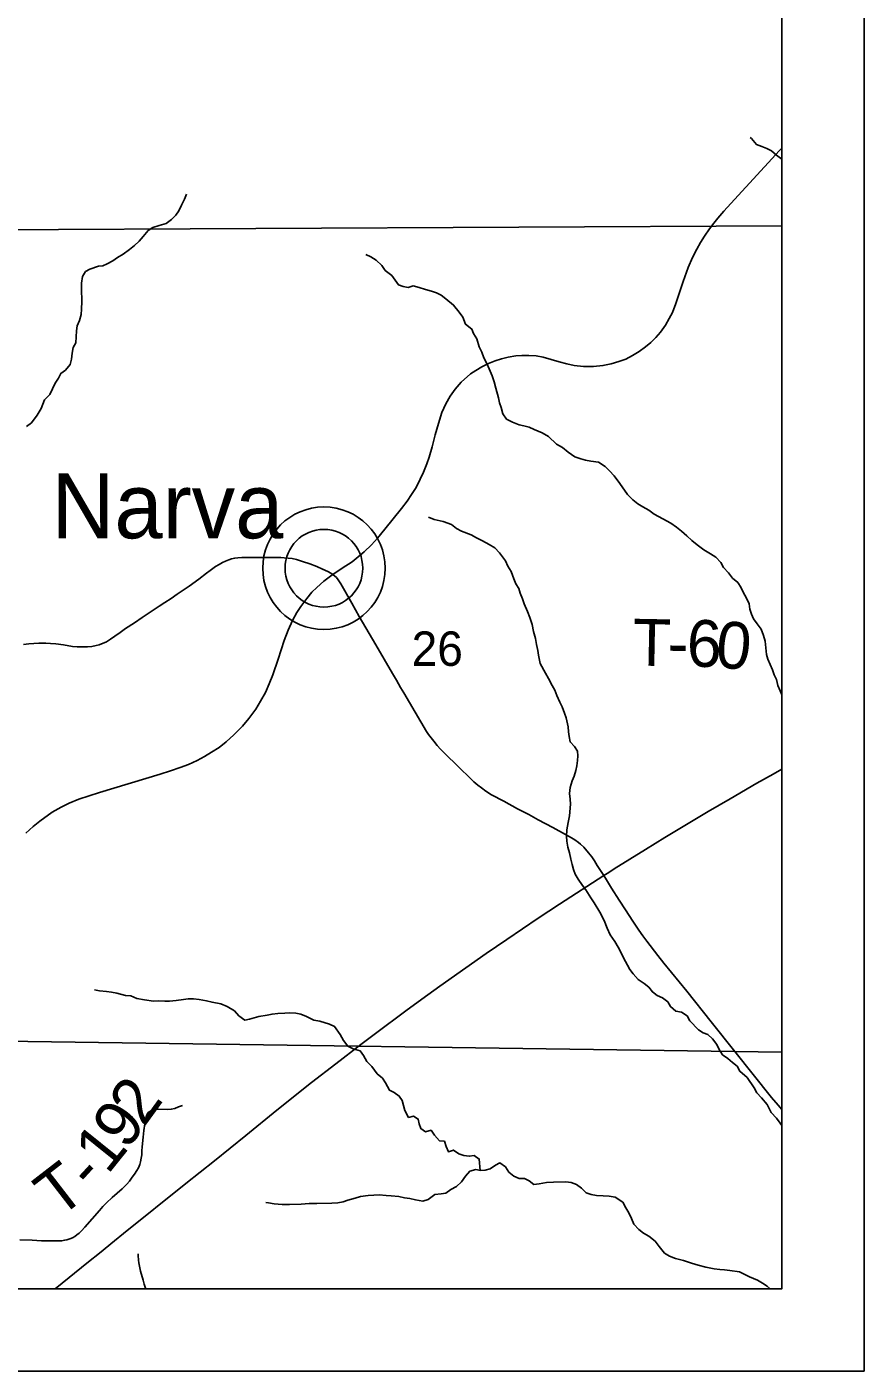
# Model space of a CAD drawing. Extents: x 0 to 34, y 0 to 22.
# Drawn here: x 16.483 to 17.5, y 13.5 to 15.132 of the extents above; entities that cross this region are included whole.
import ezdxf

# ---------------------------------------------------------------- set-up
doc = ezdxf.new("R2010")
doc.units = 0
for name, color, linetype in [('GM_X_Corporation', 7, 'Continuous'), ('GM_X_County_Road', 7, 'Continuous'), ('GM_X_Minor_River', 7, 'Continuous'), ('GM_X_Rail_Line', 7, 'Continuous'), ('GM_X_Section_Text', 7, 'Continuous'), ('GM_X_Township_Road', 7, 'Continuous'), ('GM_X_Township_Road_Text', 7, 'Continuous'), ('GM_X_Unincorporated', 7, 'Continuous'), ('GM_X_Unincorporated_Location', 7, 'Continuous'), ('GM_X_Unincorporated_Text', 7, 'Continuous'), ('GM_X_US_Route', 7, 'Continuous'), ('SH_Data', 7, 'Continuous')]:
    doc.layers.add(name, color=color, linetype=linetype)

msp = doc.modelspace()

# ---------------------------------------------------------------- linework, layer by layer
at = {"layer": 'GM_X_Corporation'}
for points in [[(16.4214, 13.6), (17.4, 13.6), (17.4, 16.913), (16.5516, 16.9243), (16.4689, 16.9245), (16.4603, 16.2617), (16.4611, 16.1288), (16.4516, 15.5964), (16.4498, 15.4626), (16.4419, 14.8642), (16.438, 14.5908), (16.4339, 14.3806), (16.4212, 13.6609)], [(17.4, 14.8906), (17.4, 15.8967), (16.4563, 15.9084), (16.441, 14.8856)], [(17.4, 13.8871), (17.4, 14.8906), (16.441, 14.8856), (16.4262, 13.901)], [(16.4212, 13.6), (17.4, 13.6), (17.4, 13.8871), (16.4262, 13.901)]]:
    msp.add_lwpolyline(points, close=True, dxfattribs=at)
at = {"layer": 'GM_X_County_Road'}
for points in [[(16.4786, 14.3823), (16.4851, 14.3829), (16.4912, 14.3835), (16.4971, 14.3838), (16.5014, 14.3839), (16.5055, 14.3839), (16.5112, 14.3835), (16.5178, 14.383), (16.5272, 14.3818), (16.538, 14.38), (16.5438, 14.3795), (16.5475, 14.3793), (16.5565, 14.3795), (16.5615, 14.38), (16.5668, 14.3809), (16.5703, 14.382), (16.5732, 14.3829), (16.5764, 14.3843), (16.5793, 14.3857), (16.5844, 14.3888), (16.5896, 14.3925), (16.5962, 14.3968), (16.6027, 14.4015), (16.6135, 14.4086), (16.6228, 14.4151), (16.6323, 14.4215), (16.6434, 14.4288), (16.6502, 14.4333), (16.6578, 14.4383), (16.6653, 14.4432), (16.68, 14.453), (16.6915, 14.4616), (16.7009, 14.4687), (16.7053, 14.4721), (16.7118, 14.4768), (16.7163, 14.4796), (16.7202, 14.4818), (16.7241, 14.4836), (16.728, 14.4851), (16.7313, 14.4861), (16.7353, 14.4871), (16.7391, 14.4875), (16.7437, 14.4881), (16.7481, 14.4881), (16.7851, 14.4879), (16.7914, 14.4878), (16.7951, 14.4877), (16.8001, 14.4872), (16.8049, 14.4865), (16.8104, 14.4853), (16.8177, 14.4832), (16.8264, 14.4804), (16.8351, 14.4769), (16.842, 14.4739), (16.8484, 14.4709), (16.8518, 14.4689), (16.8538, 14.4678), (16.8566, 14.4657), (16.859, 14.4635), (16.8611, 14.4608), (16.8641, 14.4561), (16.8774, 14.4323), (16.8866, 14.4162), (16.9066, 14.3819), (16.9268, 14.3472), (16.9317, 14.3389), (16.9367, 14.3302), (16.9406, 14.3235), (16.9475, 14.3117), (16.9682, 14.2766), (16.9708, 14.273), (16.974, 14.2688), (16.9771, 14.2649), (16.9814, 14.2598), (16.9854, 14.2551), (16.9938, 14.2466), (17.0035, 14.2372), (17.0258, 14.2154), (17.0305, 14.2113), (17.0349, 14.2081), (17.0403, 14.2042), (17.0474, 14.1998), (17.0621, 14.1922), (17.079, 14.1828), (17.0924, 14.1757), (17.1039, 14.1695), (17.1217, 14.1601), (17.1371, 14.1516), (17.1445, 14.1477), (17.1486, 14.145), (17.1528, 14.142), (17.1553, 14.1399), (17.1595, 14.1362), (17.1651, 14.1295), (17.1692, 14.1243), (17.1722, 14.1196), (17.1758, 14.1141), (17.1837, 14.1017)], [(17.1837, 14.1017), (17.1868, 14.0965), (17.193, 14.0864), (17.2023, 14.0719), (17.2099, 14.0601), (17.2189, 14.0462), (17.2263, 14.0354), (17.2311, 14.0287), (17.2361, 14.0219), (17.2492, 14.0048), (17.2568, 13.9953), (17.2847, 13.9614), (17.3143, 13.9242), (17.343, 13.8879), (17.3876, 13.8323), (17.3954, 13.8228), (17.4, 13.8175)]]:
    msp.add_lwpolyline(points, dxfattribs=at)
at = {"layer": 'GM_X_Minor_River'}
for points in [[(17.4, 14.9714), (17.3935, 14.9764), (17.3876, 14.9816), (17.3819, 14.9845), (17.3757, 14.987), (17.3692, 14.9895), (17.363, 14.9965), (17.3614, 14.9979)], [(16.6302, 14.8848), (16.6358, 14.8888), (16.6433, 14.8909), (16.652, 14.8934), (16.6583, 14.8985), (16.6635, 14.9035), (16.6675, 14.909), (16.6704, 14.9159), (16.674, 14.9228), (16.6765, 14.929)], [(16.4821, 14.6469), (16.4881, 14.6516), (16.4951, 14.6606), (16.5002, 14.6687), (16.5041, 14.6794), (16.5104, 14.686), (16.5136, 14.6926), (16.5169, 14.6995), (16.5209, 14.7057), (16.5238, 14.7115), (16.5297, 14.7154), (16.5353, 14.7224), (16.537, 14.7289), (16.5376, 14.7362), (16.5389, 14.743), (16.5422, 14.7484), (16.543, 14.7633), (16.5439, 14.7694), (16.5468, 14.7755), (16.5485, 14.7828), (16.5491, 14.7893), (16.5493, 14.7988), (16.5489, 14.814), (16.5491, 14.8212), (16.5504, 14.8289), (16.5537, 14.835), (16.5593, 14.8382), (16.5695, 14.8415), (16.5751, 14.842), (16.5804, 14.8444), (16.5871, 14.848), (16.5927, 14.852), (16.5998, 14.8563), (16.6073, 14.8618), (16.6136, 14.8669), (16.6191, 14.872), (16.6239, 14.8775), (16.6302, 14.8848)], [(17.0654, 14.6557), (17.061, 14.6625), (17.0589, 14.67), (17.0569, 14.6757), (17.0556, 14.6817), (17.0523, 14.6934), (17.0506, 14.7014), (17.0481, 14.7085), (17.0445, 14.7168), (17.0417, 14.7236), (17.0381, 14.7303), (17.0353, 14.7371), (17.0321, 14.7439), (17.0292, 14.7533), (17.0252, 14.7597), (17.0232, 14.7653), (17.0158, 14.7712), (17.0122, 14.7799), (17.0079, 14.7859), (17.0012, 14.7944), (16.9919, 14.8018), (16.9861, 14.8066), (16.9804, 14.8091), (16.9742, 14.8113), (16.967, 14.8134), (16.9593, 14.8158), (16.9521, 14.8176), (16.946, 14.8159), (16.9399, 14.8169), (16.9342, 14.819), (16.9303, 14.8246), (16.926, 14.8302), (16.9182, 14.8365), (16.9139, 14.8425), (16.9069, 14.8491), (16.9004, 14.8528), (16.8946, 14.856)], [(17.4, 14.3211), (17.398, 14.3259), (17.3951, 14.3323), (17.3934, 14.3399), (17.3906, 14.3455), (17.3886, 14.3515), (17.383, 14.3643), (17.3813, 14.37), (17.3807, 14.3783), (17.3798, 14.3863), (17.3777, 14.3931), (17.3748, 14.401), (17.3701, 14.4074), (17.3654, 14.4133), (17.363, 14.419), (17.361, 14.425), (17.3604, 14.4318), (17.3568, 14.4393), (17.3536, 14.445), (17.3501, 14.4517), (17.3465, 14.4577), (17.3399, 14.4629), (17.3352, 14.4692), (17.3293, 14.4759), (17.3258, 14.4819), (17.3199, 14.4882), (17.3134, 14.4923), (17.3053, 14.4974), (17.2972, 14.5033), (17.2906, 14.5084), (17.2844, 14.5144), (17.2782, 14.5199), (17.272, 14.5247), (17.265, 14.5295), (17.2554, 14.5349), (17.245, 14.5404), (17.2385, 14.5452), (17.2311, 14.5496), (17.225, 14.5532), (17.2188, 14.558), (17.2126, 14.5643), (17.2031, 14.5778), (17.1961, 14.5871), (17.1906, 14.593), (17.1852, 14.5986), (17.1774, 14.6037), (17.1679, 14.605), (17.1615, 14.606), (17.1557, 14.6078), (17.1484, 14.6102), (17.1403, 14.6157), (17.1334, 14.6213), (17.1264, 14.6257), (17.1163, 14.6349), (17.1087, 14.6393), (17.0991, 14.6432), (17.0929, 14.6461), (17.0864, 14.6479), (17.0807, 14.6489), (17.0727, 14.6521), (17.0654, 14.6557)], [(17.1268, 14.3203), (17.124, 14.3267), (17.1208, 14.3323), (17.1165, 14.341), (17.1129, 14.3473), (17.1065, 14.3594), (17.1044, 14.3692), (17.1035, 14.3749), (17.1018, 14.3824), (17.1008, 14.3896), (17.0984, 14.3979), (17.0966, 14.4066), (17.0938, 14.4149), (17.0909, 14.4225), (17.0869, 14.4315), (17.0848, 14.4379), (17.082, 14.4447), (17.0804, 14.4504), (17.0768, 14.456), (17.0744, 14.462), (17.0711, 14.471), (17.0672, 14.4774), (17.0643, 14.4838), (17.0569, 14.4935), (17.0514, 14.4998), (17.0445, 14.5038), (17.0364, 14.5082), (17.0291, 14.5118), (17.0226, 14.5155), (17.0107, 14.5197), (17.0046, 14.523), (16.9988, 14.5278), (16.9884, 14.5317), (16.9774, 14.5341), (16.9705, 14.537)], [(17.4, 13.7983), (17.3981, 13.8011), (17.3934, 13.807), (17.3872, 13.8141), (17.382, 13.8239), (17.3754, 13.8317), (17.3695, 13.838), (17.3663, 13.844), (17.3577, 13.8567), (17.3491, 13.8641), (17.3459, 13.8701), (17.3401, 13.8749), (17.3343, 13.8794), (17.3281, 13.8841), (17.3238, 13.8905), (17.321, 13.8965), (17.3159, 13.9036), (17.3101, 13.9088), (17.3043, 13.9109), (17.2986, 13.9142), (17.2884, 13.9254), (17.2848, 13.9314), (17.2779, 13.9358), (17.271, 13.9371), (17.2648, 13.9427), (17.2613, 13.9483), (17.2551, 13.9531), (17.2486, 13.9559), (17.2428, 13.9604), (17.2385, 13.966), (17.2327, 13.9708), (17.2253, 13.9755), (17.2195, 13.9822), (17.2152, 13.9878), (17.2072, 14.0028), (17.2044, 14.0088), (17.2012, 14.0149), (17.1972, 14.0216), (17.1913, 14.0298), (17.1877, 14.0377), (17.1841, 14.0471), (17.1789, 14.0573), (17.1718, 14.0685), (17.1679, 14.0745), (17.1619, 14.0842), (17.1576, 14.0898), (17.1525, 14.0973), (17.1489, 14.1033), (17.1469, 14.109), (17.1452, 14.115), (17.1435, 14.1218), (17.1418, 14.1294), (17.1398, 14.1362), (17.1388, 14.1434), (17.1383, 14.1494), (17.1389, 14.1571), (17.1402, 14.1662), (17.1418, 14.1743), (17.1434, 14.1884), (17.1429, 14.1944), (17.1419, 14.2013), (17.1429, 14.2085), (17.1454, 14.2166), (17.1475, 14.2223), (17.1496, 14.2292), (17.151, 14.235), (17.1519, 14.2414), (17.1522, 14.2472), (17.1517, 14.2528), (17.1481, 14.2585), (17.1427, 14.264), (17.1414, 14.2705), (17.1408, 14.2762), (17.1403, 14.2822), (17.1378, 14.2932), (17.1361, 14.2989), (17.1329, 14.3064), (17.1304, 14.3124), (17.1268, 14.3203)], [(17.0335, 13.7435), (17.0323, 13.7574), (17.0261, 13.7618), (17.0201, 13.7608), (17.0136, 13.7618), (17.0075, 13.764), (17.0009, 13.7684), (16.9949, 13.7663), (16.9921, 13.7727), (16.99, 13.7791), (16.984, 13.7797), (16.9781, 13.7864), (16.9738, 13.7924), (16.967, 13.7907), (16.9612, 13.7944), (16.9592, 13.8004), (16.9583, 13.8061), (16.9525, 13.8094), (16.9465, 13.8081), (16.9421, 13.8163), (16.9387, 13.8284), (16.9352, 13.834), (16.929, 13.8384), (16.9233, 13.841), (16.9185, 13.85), (16.9149, 13.8556), (16.9083, 13.8611), (16.9017, 13.8697), (16.8958, 13.876), (16.8915, 13.8831), (16.8875, 13.8887), (16.8791, 13.8912), (16.8726, 13.8945), (16.8675, 13.9016), (16.8635, 13.9087), (16.8565, 13.9184), (16.8503, 13.9213), (16.8385, 13.9248), (16.8312, 13.9261), (16.8224, 13.9305), (16.8155, 13.9333), (16.8094, 13.9347), (16.8022, 13.9349), (16.7961, 13.9348), (16.7874, 13.9342), (16.7806, 13.9336), (16.7745, 13.9323), (16.7647, 13.9306), (16.7587, 13.9289), (16.753, 13.9272), (16.7474, 13.9263), (16.7404, 13.9315), (16.735, 13.9374), (16.7261, 13.9429), (16.7184, 13.9461), (16.7078, 13.9478), (16.7009, 13.9495), (16.6921, 13.9512), (16.6853, 13.9522), (16.6788, 13.952), (16.6728, 13.9511), (16.6641, 13.9501), (16.6561, 13.9491), (16.6501, 13.949), (16.6421, 13.9496), (16.6364, 13.9494), (16.6257, 13.9507), (16.6162, 13.9523), (16.6089, 13.9556), (16.6025, 13.9562), (16.5918, 13.9589), (16.5853, 13.9603), (16.5796, 13.9609), (16.5708, 13.9618), (16.5647, 13.9628)], [(17.3857, 13.6), (17.3822, 13.6033), (17.3764, 13.6066), (17.3706, 13.6103), (17.3607, 13.6146), (17.3484, 13.6207), (17.337, 13.622), (17.3305, 13.6229), (17.3248, 13.6232), (17.3179, 13.6242), (17.3076, 13.6262), (17.2985, 13.6286), (17.2904, 13.6311), (17.2805, 13.6342), (17.2709, 13.6367), (17.2637, 13.6395), (17.2575, 13.6432), (17.2509, 13.6514), (17.2461, 13.6577), (17.2384, 13.664), (17.2319, 13.6676), (17.2261, 13.6721), (17.2202, 13.6784), (17.2174, 13.6855), (17.2142, 13.6923), (17.2106, 13.6983), (17.2066, 13.705), (17.1974, 13.7113), (17.1901, 13.7126), (17.1829, 13.7128), (17.1749, 13.7134), (17.1685, 13.7144), (17.1623, 13.7165), (17.1565, 13.722), (17.1503, 13.7265), (17.1442, 13.729), (17.1377, 13.7299), (17.1226, 13.7296), (17.1142, 13.729), (17.1052, 13.7276), (17.0987, 13.7267), (17.0929, 13.7311), (17.0872, 13.734), (17.0807, 13.7338), (17.0742, 13.7367), (17.0684, 13.7415), (17.0641, 13.7479), (17.0575, 13.7527), (17.0519, 13.7499), (17.0455, 13.7455), (17.0395, 13.7438), (17.0338, 13.7437), (17.0281, 13.7447), (17.0209, 13.7426), (17.0158, 13.7368), (17.0106, 13.7298), (17.0047, 13.724), (16.998, 13.7204), (16.9916, 13.716), (16.986, 13.7151), (16.9784, 13.7145), (16.9702, 13.7083), (16.9638, 13.7062), (16.955, 13.7079), (16.9478, 13.7096), (16.9417, 13.7106), (16.9348, 13.7119), (16.9253, 13.7128), (16.9192, 13.7134), (16.9109, 13.714), (16.9044, 13.7138), (16.8972, 13.7133), (16.8881, 13.7119), (16.8817, 13.7099), (16.8727, 13.7077), (16.8671, 13.7057), (16.8606, 13.7044), (16.8531, 13.7038), (16.8349, 13.7034), (16.8258, 13.7035), (16.8159, 13.7029), (16.8019, 13.7025)], [(16.8019, 13.7025), (16.7928, 13.7023), (16.7833, 13.7032), (16.7764, 13.7042), (16.7732, 13.7049)]]:
    msp.add_lwpolyline(points, dxfattribs=at)
at = {"layer": 'GM_X_Rail_Line'}
msp.add_lwpolyline([(16.4813, 14.1531), (16.4903, 14.1614), (16.4984, 14.1679), (16.5134, 14.1786), (16.5245, 14.1847), (16.5342, 14.1895), (16.5458, 14.1944), (16.5708, 14.2025), (16.6445, 14.2248), (16.6573, 14.2288), (16.6691, 14.2329), (16.6789, 14.2366), (16.6896, 14.2414), (16.6986, 14.2461), (16.7071, 14.2514), (16.7163, 14.2574), (16.7247, 14.2642), (16.7343, 14.2727), (16.7445, 14.2831), (16.7525, 14.2924), (16.7609, 14.3039), (16.7667, 14.3135), (16.7726, 14.3239), (16.7771, 14.3344), (16.7817, 14.3455), (16.788, 14.3646), (16.7954, 14.387), (16.8001, 14.3996), (16.8055, 14.4116), (16.8107, 14.4212), (16.8155, 14.4285), (16.8227, 14.4381), (16.829, 14.4458), (16.835, 14.4516), (16.8433, 14.4591), (16.8532, 14.4665), (16.8659, 14.475), (16.8778, 14.4826), (16.8926, 14.4946), (16.9013, 14.5033), (16.9085, 14.5115), (16.9177, 14.5224), (16.9377, 14.5474), (16.9446, 14.5565), (16.95, 14.5643), (16.9557, 14.5729), (16.9607, 14.583), (16.9647, 14.5917), (16.9687, 14.6018), (16.9715, 14.6099), (16.975, 14.6221), (16.9787, 14.637), (16.9827, 14.6508), (16.9868, 14.6639), (16.9916, 14.6746), (16.9971, 14.684), (17.003, 14.6923), (17.0105, 14.7008), (17.0219, 14.7108), (17.0283, 14.7151), (17.0353, 14.7194), (17.0434, 14.7236), (17.0515, 14.7268), (17.0593, 14.7293), (17.0676, 14.7311), (17.0769, 14.7329), (17.0842, 14.7332), (17.0927, 14.7332), (17.1015, 14.7326), (17.1101, 14.7313), (17.1294, 14.7256), (17.1387, 14.7232), (17.1478, 14.7212), (17.159, 14.7198), (17.171, 14.7198), (17.1825, 14.721), (17.1927, 14.723), (17.202, 14.7259), (17.2103, 14.7288), (17.2185, 14.733), (17.2267, 14.7382), (17.2342, 14.7436), (17.2408, 14.7491), (17.2467, 14.755), (17.2524, 14.7615), (17.2585, 14.77), (17.2632, 14.7781), (17.267, 14.7855), (17.2713, 14.7962), (17.2801, 14.8232), (17.2861, 14.8401), (17.2914, 14.8521), (17.2967, 14.8622), (17.3011, 14.8702), (17.3061, 14.8782), (17.3122, 14.8868), (17.3172, 14.894), (17.3223, 14.8999), (17.3295, 14.9085), (17.338, 14.9176), (17.397, 14.9821), (17.4, 14.9851)], dxfattribs=at)
at = {"layer": 'GM_X_Township_Road'}
for points in [[(16.4743, 13.6594), (16.4891, 13.6588), (16.5003, 13.6583), (16.514, 13.6582), (16.5251, 13.6583), (16.5285, 13.6588), (16.5314, 13.6595), (16.535, 13.6605), (16.5379, 13.6617), (16.5409, 13.6635), (16.5433, 13.6653), (16.5461, 13.6675), (16.5491, 13.6704), (16.5532, 13.6749), (16.571, 13.6952), (16.5751, 13.6997), (16.5794, 13.7044), (16.5861, 13.7109), (16.5983, 13.7213), (16.6013, 13.7241), (16.604, 13.727), (16.6072, 13.7307), (16.6108, 13.7355), (16.6134, 13.7391), (16.6161, 13.7434), (16.6181, 13.747), (16.6198, 13.7508), (16.6208, 13.7543), (16.6217, 13.7584), (16.6222, 13.7627), (16.6225, 13.7676), (16.6229, 13.7724), (16.6238, 13.7842), (16.6248, 13.7923), (16.6261, 13.8002), (16.6273, 13.8067), (16.6277, 13.8086), (16.6286, 13.8112), (16.6298, 13.8135), (16.6314, 13.8149), (16.634, 13.8163), (16.6366, 13.8172), (16.6399, 13.8178), (16.643, 13.8179), (16.654, 13.8176), (16.6581, 13.818), (16.6624, 13.819), (16.6671, 13.8207), (16.6719, 13.8226)], [(16.6178, 13.6425), (16.6178, 13.6404), (16.6183, 13.6347), (16.6188, 13.6316), (16.6199, 13.6256), (16.6209, 13.6212), (16.6238, 13.6105), (16.6252, 13.6054), (16.6267, 13.6008), (16.627, 13.6)]]:
    msp.add_lwpolyline(points, dxfattribs=at)
at = {"layer": 'GM_X_Unincorporated'}
for radius in [0.0744, 0.0472]:
    msp.add_circle((16.8436, 14.4749), radius, dxfattribs=at)
at = {"layer": 'GM_X_Unincorporated_Location'}
msp.add_line((16.8436, 14.4749), (16.8436, 14.4749), dxfattribs=at)
at = {"layer": 'GM_X_US_Route'}
msp.add_lwpolyline([(16.5169, 13.6), (16.5576, 13.6327), (16.571, 13.6434), (16.5892, 13.658), (16.6002, 13.6669), (16.6757, 13.7277), (16.7105, 13.7555), (16.7486, 13.7861), (16.7865, 13.8168), (16.8285, 13.8503), (16.8579, 13.8733), (16.8885, 13.8965), (16.9063, 13.9098), (16.9433, 13.9374), (16.9627, 13.9517), (16.9844, 13.9676), (17.0159, 13.9897), (17.0409, 14.007), (17.0657, 14.024), (17.1041, 14.05), (17.1299, 14.0669), (17.1837, 14.1017), (17.1897, 14.1056), (17.1963, 14.1097), (17.2342, 14.1334), (17.2578, 14.1479), (17.3106, 14.1795), (17.3371, 14.1949), (17.3698, 14.2138), (17.3896, 14.225), (17.4, 14.2307)], dxfattribs=at)
at = {"layer": 'SH_Data'}
for points in [[(10.5, 20.5), (17.5, 20.5), (17.5, 13.5), (10.5, 13.5)], [(10.6, 20.4), (17.4, 20.4), (17.4, 13.6), (10.6, 13.6)]]:
    msp.add_lwpolyline(points, close=True, dxfattribs=at)

# ---------------------------------------------------------------- texts
at = {"layer": 'GM_X_Section_Text'}
msp.add_text('26', height=0.04186, rotation=0, dxfattribs=at).set_placement((16.9502, 14.3563))
at = {"layer": 'GM_X_Township_Road_Text'}
for s, rotation, p in [('T', 358.89, (17.2183, 14.3568)), ('6', 358.9593, (17.2842, 14.3555)), ('0', 354.5121, (17.318, 14.355)), ('-', 358.8957, (17.2608, 14.356)), ('2', 54.0401, (16.6248, 13.7953)), ('9', 54.1637, (16.6044, 13.7672)), ('1', 51.2389, (16.5808, 13.7376)), ('T', 37.6962, (16.5211, 13.6844)), ('-', 47.3806, (16.5624, 13.7174))]:
    msp.add_text(s, height=0.0568, rotation=rotation, dxfattribs=at).set_placement(p)
at = {"layer": 'GM_X_Unincorporated_Text'}
msp.add_text('Narva', height=0.07898, rotation=0, dxfattribs=at).set_placement((16.5127, 14.5112))

doc.saveas('drawing.dxf')
